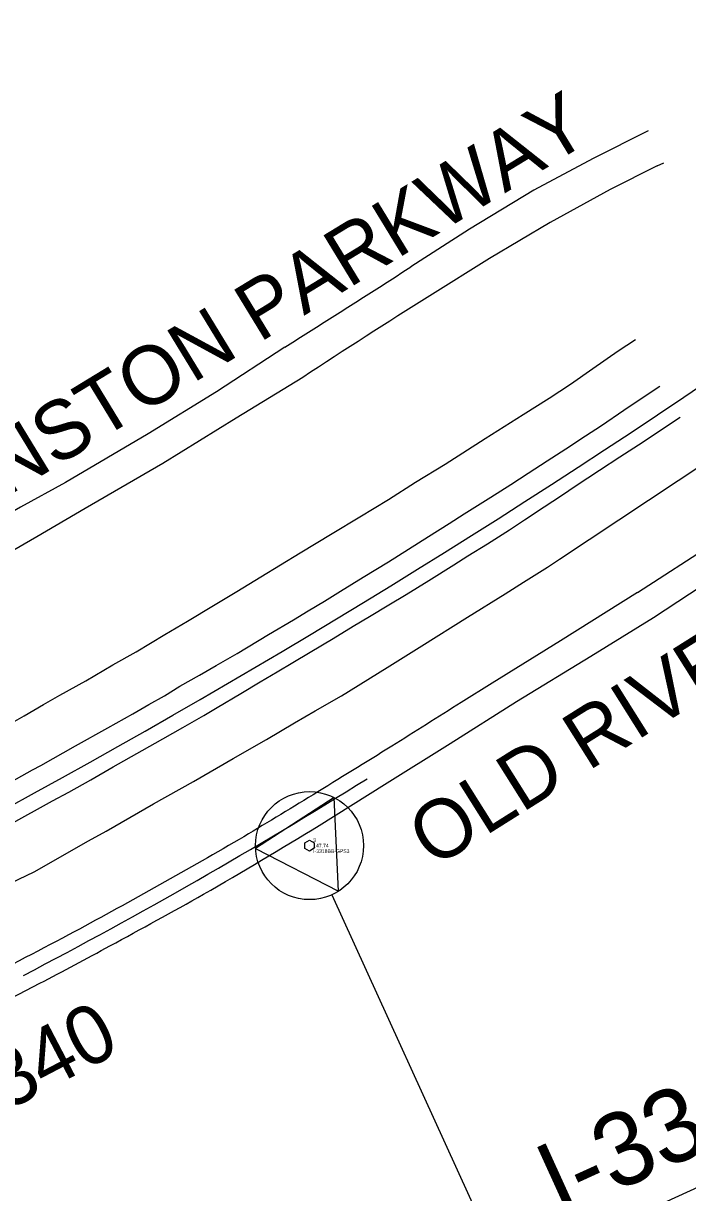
# Model space of a CAD drawing. Extents: x 2243531 to 2252747, y 658714 to 667210.
# Drawn here: x 2250172 to 2250626, y 663667 to 664465 of the extents above; entities that cross this region are included whole.
import ezdxf

# ---------------------------------------------------------------- set-up
doc = ezdxf.new("R2010")
doc.units = 0
for name, color, linetype in [('CTL GPS Vertical CELL', 7, 'Continuous'), ('CTL GPS Vertical Cogo Comment', 7, 'Continuous'), ('CTL GPS Vertical Cogo Elevation', 7, 'Continuous'), ('CTL GPS Vertical Cogo Number', 7, 'Continuous'), ('CTL NGS Horizontal CELL', 7, 'Continuous'), ('CTL Supplemental Horizontal and Vertical Text', 7, 'Continuous'), ('Exist Roads EOP', 7, 'Continuous'), ('Exist Roads EOP Text', 7, 'Continuous'), ('Prop Horizontal Alignment', 7, 'Continuous')]:
    doc.layers.add(name, color=color, linetype=linetype)

msp = doc.modelspace()

# ---------------------------------------------------------------- linework, layer by layer
at = {"layer": 'CTL GPS Vertical CELL'}
msp.add_line((2250367.8, 663904.08), (2250367.8, 663904.08), dxfattribs=at)
msp.add_lwpolyline([(2250364.57, 663905.96), (2250367.82, 663907.77), (2250371.07, 663905.98), (2250371.02, 663902.26), (2250367.77, 663900.37), (2250364.57, 663902.18)], close=True, dxfattribs=at)
at = {"layer": 'CTL NGS Horizontal CELL'}
for p, q in [((2250367.8, 663904.08), (2250367.8, 663904.08)), ((2250383.09, 663870.53), (2250501.32, 663611.07)), ((2250501.32, 663611.07), (2251034.19, 663853.89))]:
    msp.add_line(p, q, dxfattribs=at)
msp.add_lwpolyline([(2250330.94, 663902.15), (2250387.59, 663872.91), (2250384.72, 663936.85), (2250330.94, 663902.15)], dxfattribs=at)
msp.add_circle((2250367.8, 663904.08), 36.87, dxfattribs=at)
at = {"layer": 'Exist Roads EOP'}
for p, q in [((2250605.16, 664367.95), (2250605.16, 664367.95)), ((2250605.16, 664367.95), (2250605.16, 664367.95)), ((2250538.42, 664099.52), (2250639.73, 664166.68)), ((2250591.62, 664076.77), (2250671.26, 664128.23)), ((2250602.62, 664059.87), (2250682.84, 664112.38))]:
    msp.add_line(p, q, dxfattribs=at)
for points in [[(2250599.04, 664391.82), (2250561.36, 664372.97), (2250520.93, 664351.32), (2250476.95, 664324.84), (2250436.87, 664299.02)], [(2250599.04, 664391.82), (2250561.36, 664372.97), (2250520.93, 664351.32), (2250476.95, 664324.84), (2250436.87, 664299.02)], [(2250605.16, 664367.95), (2250573.13, 664351.84), (2250532.18, 664329.41), (2250490.55, 664304.72), (2250449.83, 664279.35)], [(2250605.16, 664367.95), (2250573.13, 664351.84), (2250532.18, 664329.41), (2250490.55, 664304.72), (2250449.83, 664279.35)], [(2250605.16, 664367.95), (2250609.63, 664370.05)], [(2250605.16, 664367.95), (2250609.63, 664370.05)], [(2250158.72, 663984.49), (2250173.08, 663992.65), (2250186.18, 664000.31), (2250197.31, 664006.67), (2250215.1, 664016.62), (2250233.43, 664027.41), (2250249.39, 664036.4), (2250269.12, 664048.17), (2250284.51, 664057.25), (2250302.23, 664067.92), (2250318.12, 664077.39), (2250334.59, 664087.62), (2250361.36, 664103.91), (2250383.32, 664117.15), (2250402.14, 664128.47), (2250421.72, 664140.22), (2250440.22, 664152.06), (2250460.38, 664164.36), (2250487.7, 664181.91), (2250513.64, 664198.21), (2250531.42, 664209.42), (2250545.89, 664219), (2250561.12, 664229.73), (2250578.6, 664241.65), (2250590.36, 664249.55)], [(2250158.72, 663984.49), (2250173.08, 663992.65), (2250186.18, 664000.31), (2250197.31, 664006.67), (2250215.1, 664016.62), (2250233.43, 664027.41), (2250249.39, 664036.4), (2250269.12, 664048.17), (2250284.51, 664057.25), (2250302.23, 664067.92), (2250318.12, 664077.39), (2250334.59, 664087.62), (2250361.36, 664103.91), (2250383.32, 664117.15), (2250402.14, 664128.47), (2250421.72, 664140.22), (2250440.22, 664152.06), (2250460.38, 664164.36), (2250487.7, 664181.91), (2250513.64, 664198.21), (2250531.42, 664209.42), (2250545.89, 664219), (2250561.12, 664229.73), (2250578.6, 664241.65), (2250590.36, 664249.55)], [(2250350.92, 664244.3), (2250304.23, 664213.76), (2250257.71, 664185.06), (2250201.23, 664151.95), (2250170.4, 664135.04), (2250126.46, 664109.78), (2250081.11, 664085.14), (2250024.28, 664054.88), (2249973, 664028.37), (2249923.63, 664003.06), (2249904.64, 663993.35)], [(2250350.92, 664244.3), (2250304.23, 664213.76), (2250257.71, 664185.06), (2250201.23, 664151.95), (2250170.4, 664135.04), (2250126.46, 664109.78), (2250081.11, 664085.14), (2250024.28, 664054.88), (2249973, 664028.37), (2249923.63, 664003.06), (2249904.64, 663993.35)], [(2250363.14, 664223.59), (2250317.79, 664195.69), (2250267.69, 664164.82), (2250214.57, 664134.24), (2250181.69, 664114.86), (2250136.97, 664089.2), (2250088.78, 664062.07), (2250035.53, 664033.88), (2249981.23, 664005.75), (2249934.93, 663982.02), (2249911.9, 663970.47)], [(2250363.14, 664223.59), (2250317.79, 664195.69), (2250267.69, 664164.82), (2250214.57, 664134.24), (2250181.69, 664114.86), (2250136.97, 664089.2), (2250088.78, 664062.07), (2250035.53, 664033.88), (2249981.23, 664005.75), (2249934.93, 663982.02), (2249911.9, 663970.47)], [(2250178.7, 663955.71), (2250184.3, 663958.78), (2250208.01, 663972.15), (2250230.15, 663984.46), (2250247.17, 663993.98), (2250258.08, 664000.33), (2250268.76, 664006.34), (2250279.37, 664012.79), (2250292.66, 664020.44), (2250303.96, 664027), (2250318.34, 664035.28), (2250339.82, 664048.12), (2250356.84, 664058.09), (2250366.98, 664064.41), (2250378.07, 664070.99), (2250388.85, 664077.66), (2250404.5, 664087.39), (2250421.8, 664097.75), (2250435.44, 664106.47), (2250448.98, 664114.98), (2250463.04, 664123.99), (2250473.32, 664130.57), (2250491.66, 664141.87), (2250505.24, 664150.44), (2250517.01, 664158.29), (2250530.07, 664166.7), (2250542.68, 664174.81), (2250556.09, 664183.77), (2250567.17, 664190.9), (2250582.3, 664201.26), (2250596.34, 664210.51), (2250607.04, 664217.55)], [(2250178.7, 663955.71), (2250184.3, 663958.78), (2250208.01, 663972.15), (2250230.15, 663984.46), (2250247.17, 663993.98), (2250258.08, 664000.33), (2250268.76, 664006.34), (2250279.37, 664012.79), (2250292.66, 664020.44), (2250303.96, 664027), (2250318.34, 664035.28), (2250339.82, 664048.12), (2250356.84, 664058.09), (2250366.98, 664064.41), (2250378.07, 664070.99), (2250388.85, 664077.66), (2250404.5, 664087.39), (2250421.8, 664097.75), (2250435.44, 664106.47), (2250448.98, 664114.98), (2250463.04, 664123.99), (2250473.32, 664130.57), (2250491.66, 664141.87), (2250505.24, 664150.44), (2250517.01, 664158.29), (2250530.07, 664166.7), (2250542.68, 664174.81), (2250556.09, 664183.77), (2250567.17, 664190.9), (2250582.3, 664201.26), (2250596.34, 664210.51), (2250607.04, 664217.55)], [(2250192.4, 663934.62), (2250203.58, 663940.63), (2250218.57, 663948.92), (2250233.72, 663957.75), (2250253.46, 663969.04), (2250267.55, 663976.92), (2250281.37, 663984.68), (2250295.65, 663992.85), (2250304.79, 663998.42), (2250320.9, 664008), (2250333.99, 664015.77), (2250345.65, 664022.66), (2250356.37, 664029.01), (2250368.19, 664036.08), (2250383.84, 664045.35), (2250397.66, 664053.79), (2250408.72, 664060.43), (2250421.95, 664068.35), (2250433.77, 664075.56), (2250449.27, 664084.92), (2250466.33, 664095.71), (2250475.96, 664101.86), (2250489.27, 664110.13), (2250504.36, 664119.63), (2250514.53, 664126.31), (2250528.02, 664135.27), (2250539.82, 664142.93), (2250549.87, 664149.77), (2250565.77, 664160.32), (2250579.62, 664169.49), (2250595.49, 664179.75), (2250612.85, 664191.33), (2250620.9, 664196.55)], [(2250216.95, 663907.43), (2250229.03, 663914.01), (2250261.32, 663932.66), (2250288.6, 663947.74), (2250315.66, 663963.5), (2250338.52, 663976.56), (2250357.53, 663987.91), (2250371.72, 663996.16), (2250389.56, 664006.31), (2250420.78, 664025.66), (2250444.41, 664040.53), (2250475.74, 664059.98), (2250501.46, 664075.96), (2250513.94, 664083.95), (2250530.35, 664094.2), (2250538.42, 664099.52)], [(2250216.95, 663907.43), (2250229.03, 663914.01), (2250261.32, 663932.66), (2250288.6, 663947.74), (2250315.66, 663963.5), (2250338.52, 663976.56), (2250357.53, 663987.91), (2250371.72, 663996.16), (2250389.56, 664006.31), (2250420.78, 664025.66), (2250444.41, 664040.53), (2250475.74, 664059.98), (2250501.46, 664075.96), (2250513.94, 664083.95), (2250530.35, 664094.2), (2250538.42, 664099.52)], [(2250591.62, 664076.77), (2250539.02, 664043.93), (2250492.5, 664015.03), (2250471.41, 664001.77)], [(2250591.62, 664076.77), (2250539.02, 664043.93), (2250492.5, 664015.03), (2250471.41, 664001.77)], [(2250374.49, 663917.75), (2250418.89, 663945.78), (2250463.9, 663973.78), (2250509.18, 664002.37), (2250559.78, 664033.32), (2250602.62, 664059.87)], [(2250374.49, 663917.75), (2250418.89, 663945.78), (2250463.9, 663973.78), (2250509.18, 664002.37), (2250559.78, 664033.32), (2250602.62, 664059.87)], [(2250151.36, 663940.62), (2250178.7, 663955.71)], [(2250163.18, 663918.53), (2250192.4, 663934.62)], [(2250179.91, 663886.23), (2250216.95, 663907.43)], [(2249742.5, 663675.66), (2249776.59, 663691.66), (2249811.06, 663707.92), (2249850.56, 663726.37), (2249885.63, 663742.92), (2249932.97, 663765.08), (2249967.97, 663781.54), (2250003.28, 663798.87), (2250039.45, 663816.82), (2250072.29, 663833.2), (2250110.04, 663851.84), (2250136.3, 663864.69), (2250169.45, 663881.11), (2250179.91, 663886.23)], [(2249742.5, 663675.66), (2249776.59, 663691.66), (2249811.06, 663707.92), (2249850.56, 663726.37), (2249885.63, 663742.92), (2249932.97, 663765.08), (2249967.97, 663781.54), (2250003.28, 663798.87), (2250039.45, 663816.82), (2250072.29, 663833.2), (2250110.04, 663851.84), (2250136.3, 663864.69), (2250169.45, 663881.11), (2250179.91, 663886.23)]]:
    msp.add_lwpolyline(points, dxfattribs=at)
for centre, major_axis, ratio, start_param, end_param in [((2247335.79, 669086.95), (4123.19, 3963.64), 0.997299, 4.504152, 4.52197), ((2247335.79, 669086.95), (4123.19, 3963.64), 0.997299, 4.504152, 4.52197), ((2253434.19, 659552.82), (-5088.18, -2355.99), 0.99686, 4.841542, 4.859925), ((2253434.19, 659552.82), (-5088.18, -2355.99), 0.99686, 4.841542, 4.859925)]:
    msp.add_ellipse(centre, major_axis=major_axis, ratio=ratio, start_param=start_param, end_param=end_param, dxfattribs=at)
for points in [[(2250471.41, 664001.77), (2250423.97, 663971.94), (2250370.21, 663938.8), (2250319.7, 663908.28), (2250261.73, 663875.22), (2250203.37, 663843.21), (2250135.49, 663807.99), (2250076.16, 663777.96)], [(2250471.41, 664001.77), (2250423.97, 663971.94), (2250370.21, 663938.8), (2250319.7, 663908.28), (2250261.73, 663875.22), (2250203.37, 663843.21), (2250135.49, 663807.99), (2250076.16, 663777.96)], [(2249991.5, 663714.36), (2250048.33, 663742.16), (2250107.55, 663771.76), (2250183.63, 663810.1), (2250231.45, 663835.63), (2250295.43, 663870.92), (2250374.49, 663917.75)], [(2249991.5, 663714.36), (2250048.33, 663742.16), (2250107.55, 663771.76), (2250183.63, 663810.1), (2250231.45, 663835.63), (2250295.43, 663870.92), (2250374.49, 663917.75)]]:
    msp.add_spline(points, degree=3, dxfattribs=at)
at = {"layer": 'Prop Horizontal Alignment'}
for centre, radius, start, end in [((2247423.42, 668962.88), 5729.58, 294.43013, 308.28013), ((2248552.07, 666917.75), 3500, 297.57881, 302.00527)]:
    msp.add_arc(centre, radius, start, end, dxfattribs=at)

# ---------------------------------------------------------------- texts
at = {"layer": 'CTL GPS Vertical Cogo Comment'}
msp.add_text('I-3318BB-GPS3', height=2.5, dxfattribs=at).set_placement((2250370.3, 663899.08))
at = {"layer": 'CTL GPS Vertical Cogo Elevation'}
msp.add_text('147.74', height=2.5, dxfattribs=at).set_placement((2250370.3, 663902.83))
at = {"layer": 'CTL GPS Vertical Cogo Number'}
msp.add_text('3', height=2.5, dxfattribs=at).set_placement((2250370.3, 663906.58))
at = {"layer": 'CTL Supplemental Horizontal and Vertical Text'}
msp.add_text('I-3318BB-GPS3', height=49.9994, rotation=24.49794, dxfattribs=at).set_placement((2250538.4, 663650.24))
at = {"layer": 'Exist Roads EOP Text'}
for s, height, rotation, p in [('JOHNSTON PARKWAY', 39.9995, 31.36191, (2250069.62, 664086.18)), ('OLD RIVER RD.', 39.9995, 32.17378, (2250452.28, 663888.16)), ('SR 2340', 40, 27.61596, (2250055.64, 663667.59))]:
    msp.add_text(s, height=height, rotation=rotation, dxfattribs=at).set_placement(p)

doc.saveas('drawing.dxf')
